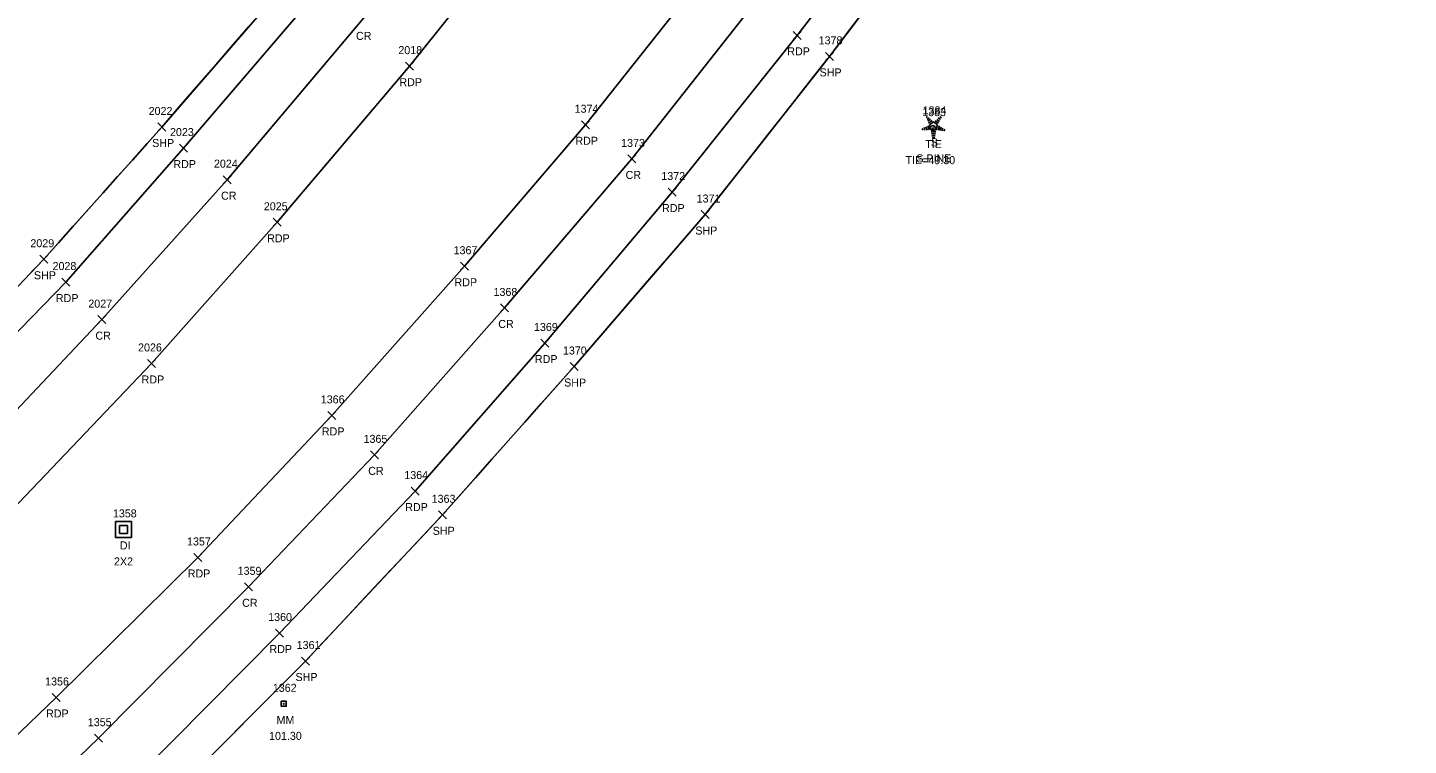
# Model space of a CAD drawing. Extents: x 1472022 to 1479249, y 777216 to 786527.
# Drawn here: x 1473041.7 to 1473386.7, y 778071.1 to 778250.4 of the extents above; entities that cross this region are included whole.
import ezdxf

# ---------------------------------------------------------------- set-up
doc = ezdxf.new("R2010")
doc.units = 0
for name, color, linetype in [('C_A', 7, 'Continuous'), ('C_C', 7, 'Continuous'), ('C_I', 7, 'Continuous'), ('CBP', 7, 'Continuous'), ('D_A', 7, 'Continuous'), ('D_C', 7, 'Continuous'), ('D_I', 7, 'Continuous'), ('DS', 7, 'Continuous'), ('L_A', 7, 'Continuous'), ('L_C', 7, 'Continuous'), ('L_I', 7, 'Continuous'), ('LSOGP', 7, 'Continuous'), ('LTC', 7, 'Continuous'), ('P_A', 7, 'Continuous'), ('P_I', 7, 'Continuous'), ('P_TIC', 7, 'Continuous'), ('PET', 7, 'Continuous'), ('PRC', 7, 'Continuous'), ('PSP', 7, 'Continuous'), ('S_A', 7, 'Continuous'), ('S_C', 7, 'Continuous'), ('S_I', 7, 'Continuous'), ('SRM', 7, 'Continuous')]:
    doc.layers.add(name, color=color, linetype=linetype)

msp = doc.modelspace()

# ---------------------------------------------------------------- linework, layer by layer
at = {"layer": 'CBP'}
for radius in [0.625, 0.0833]:
    msp.add_circle((1473267.91, 778225.3), radius, dxfattribs=at)
at = {"layer": 'DS'}
for p, q in [((1473063.68, 778127.04), (1473067.68, 778127.04)), ((1473063.68, 778123.04), (1473063.68, 778127.04)), ((1473067.68, 778127.04), (1473067.68, 778123.04)), ((1473064.68, 778124.04), (1473064.68, 778126.04)), ((1473064.68, 778126.04), (1473066.68, 778126.04)), ((1473066.68, 778124.04), (1473064.68, 778124.04)), ((1473065.68, 778125.04), (1473065.68, 778125.04)), ((1473065.68, 778125.04), (1473065.68, 778125.04)), ((1473066.68, 778126.04), (1473066.68, 778124.04)), ((1473067.68, 778123.04), (1473063.68, 778123.04))]:
    msp.add_line(p, q, dxfattribs=at)
at = {"layer": 'LSOGP'}
for points in [[(1473089.05, 778069.99), (1473093.45, 778074.42), (1473097.86, 778078.86), (1473102.27, 778083.29), (1473106.68, 778087.72), (1473111.08, 778092.16), (1473115.37, 778096.72), (1473119.66, 778101.29), (1473123.94, 778105.86), (1473128.23, 778110.42), (1473132.52, 778114.99), (1473136.8, 778119.55), (1473141.09, 778124.12), (1473145.38, 778128.69), (1473149.48, 778133.32), (1473153.59, 778137.95), (1473157.69, 778142.58), (1473161.8, 778147.21), (1473165.9, 778151.85), (1473170.01, 778156.48), (1473174.11, 778161.11), (1473178.22, 778165.74), (1473182.31, 778170.49), (1473186.41, 778175.23), (1473190.5, 778179.98), (1473194.6, 778184.72), (1473198.7, 778189.47), (1473202.79, 778194.22), (1473206.89, 778198.96), (1473210.98, 778203.71), (1473214.86, 778208.65), (1473218.75, 778213.58), (1473222.63, 778218.52), (1473226.51, 778223.46), (1473230.39, 778228.4), (1473234.27, 778233.34), (1473238.15, 778238.28), (1473242.04, 778243.22), (1473245.79, 778248.15), (1473249.54, 778253.08)], [(1473096.87, 778250.57), (1473092.55, 778245.57), (1473088.22, 778240.57), (1473083.9, 778235.58), (1473079.58, 778230.58), (1473075.26, 778225.58), (1473071.57, 778221.45), (1473067.87, 778217.32), (1473064.18, 778213.19), (1473060.49, 778209.06), (1473056.8, 778204.93), (1473053.1, 778200.8), (1473049.41, 778196.67), (1473045.72, 778192.54), (1473041.66, 778188.31)]]:
    msp.add_lwpolyline(points, dxfattribs=at)
at = {"layer": 'LTC'}
for p, q in [((1473266.21, 778227.94), (1473266.56, 778228.2)), ((1473266.42, 778227.48), (1473266.94, 778227.86)), ((1473266.62, 778227.01), (1473267.33, 778227.52)), ((1473266.83, 778226.55), (1473267.71, 778227.19)), ((1473267.06, 778226.09), (1473268.07, 778226.83)), ((1473268.07, 778226.83), (1473269.07, 778226.1)), ((1473268.49, 778227.14), (1473269.3, 778226.55)), ((1473268.86, 778227.49), (1473269.54, 778226.99)), ((1473269.23, 778227.84), (1473269.78, 778227.44)), ((1473269.6, 778228.19), (1473270.02, 778227.88)), ((1473265.24, 778225.22), (1473265.39, 778224.76)), ((1473265.69, 778225.44), (1473265.91, 778224.79)), ((1473266.15, 778225.66), (1473266.42, 778224.82)), ((1473266.6, 778225.87), (1473266.94, 778224.85)), ((1473267.06, 778226.09), (1473267.45, 778224.9)), ((1473268.68, 778224.9), (1473267.45, 778224.9)), ((1473268.64, 778224.4), (1473267.49, 778224.4)), ((1473268.55, 778223.9), (1473267.57, 778223.9)), ((1473268.47, 778223.4), (1473267.64, 778223.4)), ((1473269.07, 778226.1), (1473268.68, 778224.9)), ((1473269.51, 778225.83), (1473269.17, 778224.79)), ((1473269.95, 778225.58), (1473269.66, 778224.7)), ((1473270.39, 778225.33), (1473270.16, 778224.6)), ((1473270.84, 778225.08), (1473270.65, 778224.51)), ((1473268.39, 778222.9), (1473267.71, 778222.9))]:
    msp.add_line(p, q, dxfattribs=at)
at = {"layer": 'P_TIC'}
for points in [[(1473233.01, 778247.48), (1473235.01, 778249.48)], [(1473235.01, 778247.48), (1473233.01, 778249.48)], [(1473241.04, 778242.22), (1473243.04, 778244.22)], [(1473243.04, 778242.22), (1473241.04, 778244.22)], [(1473136.09, 778239.78), (1473138.09, 778241.78)], [(1473138.09, 778239.78), (1473136.09, 778241.78)], [(1473180.06, 778225.14), (1473182.06, 778227.14)], [(1473182.06, 778225.14), (1473180.06, 778227.14)], [(1473074.26, 778224.58), (1473076.26, 778226.58)], [(1473076.26, 778224.58), (1473074.26, 778226.58)], [(1473079.6, 778219.31), (1473081.6, 778221.31)], [(1473081.6, 778219.31), (1473079.6, 778221.31)], [(1473191.67, 778216.6), (1473193.67, 778218.6)], [(1473193.67, 778216.6), (1473191.67, 778218.6)], [(1473090.58, 778211.42), (1473092.58, 778213.42)], [(1473092.58, 778211.42), (1473090.58, 778213.42)], [(1473201.72, 778208.33), (1473203.72, 778210.33)], [(1473203.72, 778208.33), (1473201.72, 778210.33)], [(1473103.04, 778200.77), (1473105.04, 778202.77)], [(1473105.04, 778200.77), (1473103.04, 778202.77)], [(1473209.98, 778202.71), (1473211.98, 778204.71)], [(1473211.98, 778202.71), (1473209.98, 778204.71)], [(1473044.72, 778191.54), (1473046.72, 778193.54)], [(1473046.72, 778191.54), (1473044.72, 778193.54)], [(1473149.86, 778189.79), (1473151.86, 778191.79)], [(1473151.86, 778189.79), (1473149.86, 778191.79)], [(1473050.25, 778185.84), (1473052.25, 778187.84)], [(1473052.25, 778185.84), (1473050.25, 778187.84)], [(1473159.84, 778179.37), (1473161.84, 778181.37)], [(1473161.84, 778179.37), (1473159.84, 778181.37)], [(1473059.19, 778176.45), (1473061.19, 778178.45)], [(1473061.19, 778176.45), (1473059.19, 778178.45)], [(1473169.95, 778170.61), (1473171.95, 778172.61)], [(1473171.95, 778170.61), (1473169.95, 778172.61)], [(1473071.67, 778165.5), (1473073.67, 778167.5)], [(1473073.67, 778165.5), (1473071.67, 778167.5)], [(1473177.22, 778164.74), (1473179.22, 778166.74)], [(1473179.22, 778164.74), (1473177.22, 778166.74)], [(1473116.72, 778152.52), (1473118.72, 778154.52)], [(1473118.72, 778152.52), (1473116.72, 778154.52)], [(1473127.36, 778142.66), (1473129.36, 778144.66)], [(1473129.36, 778142.66), (1473127.36, 778144.66)], [(1473137.55, 778133.62), (1473139.55, 778135.62)], [(1473139.55, 778133.62), (1473137.55, 778135.62)], [(1473144.38, 778127.69), (1473146.38, 778129.69)], [(1473146.38, 778127.69), (1473144.38, 778129.69)], [(1473083.2, 778117.03), (1473085.2, 778119.03)], [(1473085.2, 778117.03), (1473083.2, 778119.03)], [(1473095.86, 778109.7), (1473097.86, 778111.7)], [(1473097.86, 778109.7), (1473095.86, 778111.7)], [(1473103.62, 778098.15), (1473105.62, 778100.15)], [(1473105.62, 778098.15), (1473103.62, 778100.15)], [(1473110.08, 778091.16), (1473112.08, 778093.16)], [(1473112.08, 778091.16), (1473110.08, 778093.16)], [(1473047.8, 778082.05), (1473049.8, 778084.05)], [(1473049.8, 778082.05), (1473047.8, 778084.05)], [(1473058.42, 778071.88), (1473060.42, 778073.88)], [(1473060.42, 778071.88), (1473058.42, 778073.88)]]:
    msp.add_lwpolyline(points, dxfattribs=at)
at = {"layer": 'PET'}
for points in [[(1472671.07, 777717.85), (1472704.16, 777745.65), (1472742.8, 777777.83), (1472783.82, 777812.54), (1472835.62, 777856.03), (1472877.54, 777891.75), (1472912.91, 777921.62), (1472958.15, 777961.39), (1472998.19, 777996.96), (1473034.38, 778029.89), (1473069.02, 778063.25), (1473104.62, 778099.15), (1473138.55, 778134.62), (1473170.95, 778171.61), (1473202.72, 778209.33), (1473234.01, 778248.48), (1473264.38, 778288.05), (1473293.42, 778328.91), (1473324.53, 778373.9), (1473351.95, 778416.72), (1473378.27, 778459.7)], [(1473255.52, 778449.63), (1473221.14, 778399.57), (1473182.52, 778345.97), (1473145.62, 778298.63), (1473115.08, 778260.59), (1473080.6, 778220.31), (1473051.25, 778186.84), (1473016.92, 778151.59), (1472979.91, 778114.91), (1472945.26, 778082.84), (1472907.77, 778049.38), (1472868.55, 778015.69), (1472837.98, 777989.81), (1472804.85, 777962.23), (1472766.82, 777929.84), (1472722.68, 777892.48), (1472682.88, 777859.11)], [(1473280.39, 778434.36), (1473245.89, 778383.45), (1473206.13, 778328.04), (1473169.71, 778281.51), (1473137.09, 778240.78), (1473104.04, 778201.77), (1473072.67, 778166.5), (1473037.86, 778129.91), (1472999.85, 778092.99), (1472964.39, 778060.83), (1472926.51, 778026.82), (1472887.44, 777993.06), (1472857.66, 777967.76), (1472824.92, 777940.5), (1472785.25, 777907.17), (1472741.34, 777869.88), (1472700.25, 777835.4), (1472658.9, 777800.89)], [(1472684.83, 777767.44), (1472722.55, 777799.22), (1472766.23, 777836.23), (1472817.16, 777878.96), (1472857.89, 777913.52), (1472893.26, 777943.27), (1472939.5, 777982.83), (1472979.03, 778017.29), (1473015.7, 778051.25), (1473048.8, 778083.05), (1473084.2, 778118.03), (1473117.72, 778153.52), (1473150.86, 778190.79), (1473181.06, 778226.14), (1473213.03, 778266.55), (1473241.58, 778304.07), (1473271.79, 778346.69), (1473301.45, 778389.87), (1473329.64, 778433.49)]]:
    msp.add_lwpolyline(points, dxfattribs=at)
at = {"layer": 'PRC'}
for points in [[(1472662.17, 777728.39), (1472695.49, 777755.92), (1472733.11, 777787.35), (1472775.04, 777822.62), (1472827.37, 777866.4), (1472869.28, 777902.04), (1472903.96, 777930.47), (1472949.73, 777971.08), (1472949.47, 777970.99), (1472989.06, 778006.22), (1473025.25, 778040), (1473059.42, 778072.88), (1473096.86, 778110.7), (1473128.36, 778143.66), (1473160.84, 778180.37), (1473192.67, 778217.6), (1473223.74, 778257.05), (1473253.58, 778296.11), (1473283.93, 778338.11), (1473313.78, 778381.5), (1473340.44, 778424.05), (1473366.77, 778467.15)], [(1473266.55, 778442.63), (1473232.46, 778392.44), (1473193.83, 778338.54), (1473156.79, 778291.23), (1473125.31, 778252.34), (1473091.58, 778212.42), (1473060.19, 778177.45), (1473026.49, 778141.75), (1472989.07, 778105.13), (1472954.29, 778073.26), (1472916.06, 778039.37), (1472877.51, 778005.85), (1472846.53, 777979.57), (1472813.91, 777952.49), (1472775.15, 777919.54), (1472731.22, 777882.43), (1472690.51, 777848.29)]]:
    msp.add_lwpolyline(points, dxfattribs=at)
at = {"layer": 'PSP'}
for points in [[(1473248.4, 778453.47), (1473214.72, 778403.13), (1473176.48, 778350.2), (1473139.45, 778301.94), (1473109.83, 778265.56), (1473075.26, 778225.58), (1473045.72, 778192.54), (1473029.49, 778175.6), (1473012.03, 778157.81), (1472973.92, 778120.85), (1472936.46, 778086.53), (1472902.36, 778055.99), (1472863.3, 778022.57), (1472832.68, 777997.03), (1472798.65, 777968.31), (1472761.65, 777936.81), (1472716.04, 777898.78), (1472676.55, 777865.69)], [(1472676.6, 777710.94), (1472709.07, 777738.21), (1472747.84, 777770.74), (1472788.89, 777806.21), (1472798.61, 777813.61), (1472840.19, 777850.33), (1472882.46, 777885.36), (1472918.99, 777916.31), (1472964.12, 777954.9), (1473004.91, 777990.69), (1473041.16, 778023.65), (1473075.83, 778056.69), (1473111.08, 778092.16), (1473145.38, 778128.69), (1473178.22, 778165.74), (1473210.98, 778203.71), (1473242.04, 778243.22), (1473272.04, 778282.69), (1473301.33, 778323.12), (1473332.33, 778368.85), (1473360.11, 778411.57), (1473386.71, 778454.12)]]:
    msp.add_lwpolyline(points, dxfattribs=at)
at = {"layer": 'SRM'}
msp.add_lwpolyline([(1473105.06, 778082.09), (1473106.31, 778082.09), (1473106.31, 778080.84), (1473105.06, 778080.84)], close=True, dxfattribs=at)
msp.add_circle((1473105.69, 778081.46), 0.0833, dxfattribs=at)

# ---------------------------------------------------------------- texts
at = {"layer": 'C_A'}
msp.add_text('TIE', height=2, dxfattribs=at).set_placement((1473265.99, 778220.3))
at = {"layer": 'C_C'}
msp.add_text('TIE=49.30', height=2, dxfattribs=at).set_placement((1473261.05, 778216.3))
at = {"layer": 'C_I'}
msp.add_text('1383', height=2, dxfattribs=at).set_placement((1473265.21, 778228.3))
at = {"layer": 'D_A'}
msp.add_text('DI', height=2, dxfattribs=at).set_placement((1473064.74, 778120.04))
at = {"layer": 'D_C'}
msp.add_text('2X2', height=2, dxfattribs=at).set_placement((1473063.26, 778116.04))
at = {"layer": 'D_I'}
msp.add_text('1358', height=2, dxfattribs=at).set_placement((1473062.99, 778128.04))
at = {"layer": 'L_A'}
msp.add_text('S', height=2, dxfattribs=at).set_placement((1473267.4, 778220.74))
at = {"layer": 'L_C'}
msp.add_text('S.PINE', height=2, dxfattribs=at).set_placement((1473263.74, 778216.74))
at = {"layer": 'L_I'}
msp.add_text('1384', height=2, dxfattribs=at).set_placement((1473265.32, 778228.74))
at = {"layer": 'LTC'}
msp.add_text('.', height=1.04, rotation=270, dxfattribs=at).set_placement((1473267.95, 778225.84))
at = {"layer": 'P_A'}
for s, p in [('CR', (1473123.74, 778247.34)), ('RDP', (1473231.5, 778243.48)), ('RDP', (1473134.57, 778235.78)), ('SHP', (1473239.57, 778238.22)), ('SHP', (1473072.8, 778220.58)), ('RDP', (1473178.55, 778221.14)), ('RDP', (1473078.09, 778215.31)), ('CR', (1473191.1, 778212.6)), ('CR', (1473090.01, 778207.42)), ('RDP', (1473200.21, 778204.33)), ('SHP', (1473208.52, 778198.71)), ('RDP', (1473101.53, 778196.77)), ('SHP', (1473043.25, 778187.54)), ('RDP', (1473148.35, 778185.79)), ('RDP', (1473048.74, 778181.84)), ('CR', (1473159.28, 778175.37)), ('CR', (1473058.62, 778172.45)), ('RDP', (1473168.44, 778166.61)), ('RDP', (1473070.16, 778161.5)), ('SHP', (1473175.75, 778160.74)), ('RDP', (1473115.21, 778148.52)), ('CR', (1473126.79, 778138.66)), ('RDP', (1473136.04, 778129.62)), ('SHP', (1473142.91, 778123.69)), ('RDP', (1473081.69, 778113.03)), ('CR', (1473095.29, 778105.7)), ('RDP', (1473102.11, 778094.15)), ('SHP', (1473108.62, 778087.16)), ('RDP', (1473046.29, 778078.05))]:
    msp.add_text(s, height=2, dxfattribs=at).set_placement(p)
at = {"layer": 'P_I'}
for s, p in [('1378', (1473239.34, 778246.22)), ('2018', (1473134.32, 778243.78)), ('2022', (1473071.92, 778228.58)), ('1374', (1473178.37, 778229.14)), ('2023', (1473077.26, 778223.31)), ('1373', (1473189.98, 778220.6)), ('2024', (1473088.24, 778215.42)), ('1372', (1473200.03, 778212.33)), ('2025', (1473100.7, 778204.77)), ('1371', (1473208.86, 778206.71)), ('2029', (1473042.37, 778195.54)), ('1367', (1473148.12, 778193.79)), ('2028', (1473047.91, 778189.84)), ('1368', (1473158.1, 778183.37)), ('2027', (1473056.85, 778180.45)), ('1369', (1473168.21, 778174.61)), ('2026', (1473069.28, 778169.5)), ('1370', (1473175.44, 778168.74)), ('1366', (1473114.93, 778156.52)), ('1365', (1473125.62, 778146.66)), ('1364', (1473135.81, 778137.62)), ('1363', (1473142.64, 778131.69)), ('1357', (1473081.51, 778121.03)), ('1359', (1473094.16, 778113.7)), ('1360', (1473101.79, 778102.15)), ('1361', (1473108.91, 778095.16)), ('1356', (1473046.05, 778086.05)), ('1355', (1473056.72, 778075.88))]:
    msp.add_text(s, height=2, dxfattribs=at).set_placement(p)
at = {"layer": 'S_A'}
msp.add_text('MM', height=2, dxfattribs=at).set_placement((1473103.88, 778076.46))
at = {"layer": 'S_C'}
msp.add_text('101.30', height=2, dxfattribs=at).set_placement((1473102.01, 778072.46))
at = {"layer": 'S_I'}
msp.add_text('1362', height=2, dxfattribs=at).set_placement((1473102.95, 778084.46))

doc.saveas('drawing.dxf')
